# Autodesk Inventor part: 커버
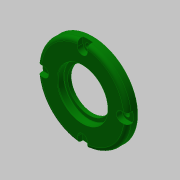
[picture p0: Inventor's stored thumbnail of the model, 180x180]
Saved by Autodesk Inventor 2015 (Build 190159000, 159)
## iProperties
Created: 2019-05
Part Number: 커버
Material: 알루미늄 6061
Document SubType Name: Modeling
Designer: mduedu
Density: 1 g/cm^3
Appearance: 진녹색
Author: mduedu
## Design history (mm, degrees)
sketch "스케치1"
  geometry: L1 (0, 0)-(36, 0); L2 (36, 0)-(36, -8); L3 (36, -8)-(0, -8); L4 (0, -8)-(0, 0); L5 (0, -8)-(26, -8); L6 (26, -8)-(26, -12); L7 (26, -12)-(0, -12); L8 (0, -12)-(0, -8)
  constraints: 16 end point, 4 parallel, 2 horizontal, 2 perpendicular
  dimensions: "d0" = 72 diameter of L2 L4; "d2" = 52 diameter of L6 L8; "d3" = 12 distance between parallel lines of L7 L1; "d4" = 4 distance between parallel lines of L7 L3
revolve "회전1" sketch "스케치1" stored, may be unused: angle "d5" = 90 deg
sketch "스케치2" dims "d6" = 62
  geometry: L1 (-4, 31)-(-4, 35.777); L2 (4, 31)-(4, 35.777); A1 r 4 centre (0, 31) between (-4, 31) and (4, 31); A2 r 36 centre (0, 0) between (-4, 35.777) and (4, 35.777) reference; A3 r 36 centre (0, 0) between (4, 35.777) and (-4, 35.777); 2 further points
  constraints: 6 point on circle, 4 end point, 2 centre point, 2 coincident, 2 tangent, 2 vertical alignment, 1 parallel, 1 vertical, 2 other
  dimensions: "d7" = 8 distance between parallel lines of L2 L1
extrude "돌출1" cut sketch "스케치2" distance "d8" = 4.4; taper "d9" = 0 deg
fillet "모깎기1" dims "d13" = 3
sketch "스케치3"
  geometry: L1 (36, -4.4)-(36, -8) reference; L2 (36, -8)-(26, -8) reference; L3 (26, -8)-(26, -12) reference; L4 (26, -12)-(-26, -12) reference; L5 (-26, -12)-(-26, -8) reference; L6 (-26, -8)-(-36, -8) reference; L7 (-36, -8)-(-36, -4.4) reference; L8 (-36, -4.4)-(-27, -4.4) reference; L9 (-27, -4.4)-(-27, 0) reference; L10 (-27, 0)-(27, 0) reference; L11 (27, 0)-(27, -4.4) reference; L12 (27, -4.4)-(36, -4.4) reference; L13 (0, 0)-(20, 0); L14 (20, 0)-(20, -5.2); L15 (20, -5.2)-(0, -5.2); L16 (0, -5.2)-(0, 0); L17 (0, -5.2)-(17, -5.2); L18 (17, -5.2)-(17, -8); L19 (17, -8)-(0, -8); L20 (0, -8)-(0, -5.2); L21 (0, -8)-(23, -8); L22 (23, -8)-(23, -12); L23 (23, -12)-(0, -12); L24 (0, -12)-(0, -8)
  constraints: 24 end point, 6 parallel, 3 horizontal, 3 perpendicular, 1 point on line
  dimensions: "d14" = 40 diameter of L14 L16; "d16" = 5.2 distance of L13.end L14.end; "d17" = 46 diameter of L22 L24; "d18" = 4 distance of L21.end L22.end; "d19" = 34 diameter of L18 L20
revolve "회전2" sketch "스케치3" stored, may be unused: angle "d20" = 90 deg
chamfer "모따기1" distance "d21" = 0.5; stored, may be unused: second distance "d22" = 2, angle "d23" = 30 deg
fillet "모깎기2" dims "d24" = 0.2
fillet "모깎기3" dims "d25" = 3
chamfer "모따기2" distance "d26" = 1; stored, may be unused: second distance "d27" = 2, angle "d28" = 30 deg
sketch "스케치4" dims "d29" = 62
  geometry: 6 further points
  constraints: 2 vertical alignment, 1 coincident, 7 other
  dimensions: "d32" = 360 deg dimension on point (0, 0) point (0, 31) (derived)
sketch "스케치5"
  geometry: 4 further points
  constraints: 4 other
hole "구멍1" sketch "스케치5" at (-31, 0), (0, -31), (31, 0), (0, 31) diameter "d34" = 4.5; stored, may be unused: countersink angle "d38" = 90 deg, drill point angle "d40" = 0 deg; dims "d35" = 6, "d36" = 4, "d37" = 2, "d39" = 8
node "솔리드1"
pattern_circular "원형 패턴1" dims angle "d11" = 360 deg
node "절단 모서리 투영1"
